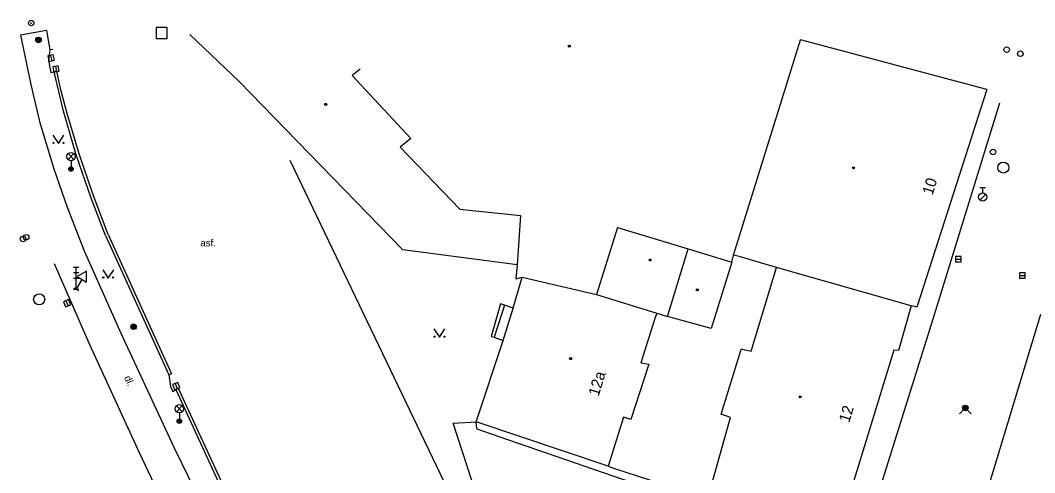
# Model space of a CAD drawing. Extents: x -598341 to -594502, y -1162301 to -1161406.
# Drawn here: x -597724.1 to -597632.3, y -1161447.8 to -1161406.9 of the extents above; entities that cross this region are included whole.
import ezdxf

# ---------------------------------------------------------------- set-up
doc = ezdxf.new("R2010")
doc.units = 0
for name, color, linetype in [('Vrstva 10', 7, 'Continuous'), ('Vrstva 11', 7, 'Continuous'), ('Vrstva 25', 7, 'Continuous'), ('Vrstva 26', 7, 'Continuous'), ('Vrstva 27', 7, 'Continuous'), ('Vrstva 28', 7, 'Continuous'), ('Vrstva 31', 7, 'Continuous'), ('Vrstva 33', 7, 'Continuous'), ('Vrstva 34', 7, 'Continuous'), ('Vrstva 36', 7, 'Continuous'), ('Vrstva 39', 7, 'Continuous'), ('Vrstva 40', 7, 'Continuous'), ('Vrstva 46', 7, 'Continuous'), ('Vrstva 5', 7, 'Continuous'), ('Vrstva 7', 7, 'Continuous')]:
    doc.layers.add(name, color=color, linetype=linetype)

msp = doc.modelspace()

# ---------------------------------------------------------------- linework, layer by layer
at = {"layer": 'Vrstva 10'}
for p, q in [((-597635.51, -1161414.4), (-597641.55, -1161433.95)), ((-597641.55, -1161433.95), (-597665.98, -1161512.17))]:
    msp.add_line(p, q, dxfattribs=at)
for points in [[(-597721.72, -1161407.83), (-597721.42, -1161409.57)], [(-597721.42, -1161409.57), (-597721.55, -1161410.54), (-597721.33, -1161411.63), (-597721.03, -1161411.55)], [(-597716.39, -1161426.38), (-597717.69, -1161422.99), (-597719.04, -1161419.07), (-597720.18, -1161415.11), (-597721.03, -1161411.55)], [(-597699.7, -1161419.56), (-597685.07, -1161450.16)], [(-597716.39, -1161426.38), (-597710.66, -1161438.99)], [(-597704.08, -1161465.47), (-597708.7, -1161455.79), (-597713.31, -1161446.04), (-597717.79, -1161436.33), (-597720.99, -1161428.95)], [(-597710.66, -1161438.99), (-597710.5, -1161440.03), (-597710.3, -1161440.48), (-597710.03, -1161440.32)], [(-597710.03, -1161440.32), (-597704.17, -1161453.05), (-597703.72, -1161454.73), (-597692.76, -1161476.87)]]:
    msp.add_lwpolyline(points, dxfattribs=at)
at = {"layer": 'Vrstva 11'}
for p, q in [((-597721.17, -1161409.54), (-597721.42, -1161409.57)), ((-597720.79, -1161411.5), (-597721.03, -1161411.55)), ((-597659.72, -1161428.8), (-597659.58, -1161428.16)), ((-597679.15, -1161429.04), (-597679.28, -1161430.29)), ((-597679.28, -1161430.29), (-597678.68, -1161430.13)), ((-597680.3, -1161432.69), (-597681.24, -1161435.57)), ((-597679.52, -1161432.94), (-597680.3, -1161432.69)), ((-597681.24, -1161435.57), (-597680.4, -1161435.88)), ((-597710.66, -1161438.99), (-597710.43, -1161438.89)), ((-597709.81, -1161440.19), (-597710.03, -1161440.32)), ((-597682.8, -1161443.87), (-597682.85, -1161443.23)), ((-597682.8, -1161443.87), (-597680.82, -1161444.57)), ((-597680.82, -1161444.57), (-597667.88, -1161449.04)), ((-597670.92, -1161447.25), (-597670.52, -1161447.4))]:
    msp.add_line(p, q, dxfattribs=at)
for points in [[(-597721.72, -1161407.83), (-597724.08, -1161408.25)], [(-597724.08, -1161408.25), (-597723.14, -1161412.69)], [(-597716.16, -1161426.29), (-597717.52, -1161422.7), (-597718.77, -1161418.99), (-597719.85, -1161415.32), (-597720.43, -1161413.19), (-597720.79, -1161411.5)], [(-597723.14, -1161412.69), (-597722.35, -1161416.05), (-597721.07, -1161420.34), (-597719.85, -1161423.8), (-597718.33, -1161427.77)], [(-597716.16, -1161426.29), (-597710.43, -1161438.89)], [(-597718.33, -1161427.77), (-597715, -1161435.22), (-597710.17, -1161445.59), (-597705.81, -1161454.55), (-597701.38, -1161464.17)], [(-597680.3, -1161432.69), (-597680.65, -1161432.57), (-597681.51, -1161435.52), (-597681.24, -1161435.57)], [(-597709.81, -1161440.19), (-597703.91, -1161452.98), (-597703.44, -1161454.64), (-597692.55, -1161476.76)], [(-597670.52, -1161447.4), (-597665.97, -1161448.88)]]:
    msp.add_lwpolyline(points, dxfattribs=at)
at = {"layer": 'Vrstva 25'}
for centre, radius in [((-597723.11, -1161407.14), 0.25), ((-597723.11, -1161407.14), 0.0303), ((-597722.45, -1161408.67), 0.25), ((-597722.45, -1161408.67), 0.2), ((-597722.45, -1161408.67), 0.15), ((-597722.45, -1161408.67), 0.1), ((-597722.45, -1161408.67), 0.05), ((-597713.85, -1161434.63), 0.25), ((-597713.85, -1161434.63), 0.2), ((-597713.85, -1161434.63), 0.15), ((-597713.85, -1161434.63), 0.1), ((-597713.85, -1161434.63), 0.05)]:
    msp.add_circle(centre, radius, dxfattribs=at)
at = {"layer": 'Vrstva 26'}
msp.add_lwpolyline([(-597711.82, -1161408.55), (-597710.82, -1161408.55), (-597710.82, -1161407.55), (-597711.82, -1161407.55)], close=True, dxfattribs=at)
at = {"layer": 'Vrstva 27'}
for p, q in [((-597721.363, -1161410.066), (-597721.256, -1161410.554)), ((-597720.923, -1161411.056), (-597720.816, -1161411.544)), ((-597639.49, -1161428.51), (-597638.99, -1161428.51)), ((-597633.69, -1161429.99), (-597633.19, -1161429.99)), ((-597719.971, -1161432.281), (-597719.769, -1161432.738)), ((-597710.085, -1161439.779), (-597709.895, -1161440.241))]:
    msp.add_line(p, q, dxfattribs=at)
for points in [[(-597721.607, -1161410.119), (-597721.501, -1161410.607), (-597721.012, -1161410.501), (-597721.118, -1161410.013)], [(-597721.167, -1161411.109), (-597721.061, -1161411.597), (-597720.572, -1161411.491), (-597720.678, -1161411.003)], [(-597639.49, -1161428.76), (-597638.99, -1161428.76), (-597638.99, -1161428.26), (-597639.49, -1161428.26)], [(-597633.69, -1161430.24), (-597633.19, -1161430.24), (-597633.19, -1161429.74), (-597633.69, -1161429.74)], [(-597720.2, -1161432.382), (-597719.997, -1161432.84), (-597719.54, -1161432.637), (-597719.743, -1161432.18)], [(-597710.316, -1161439.874), (-597710.126, -1161440.336), (-597709.664, -1161440.146), (-597709.854, -1161439.684)]]:
    msp.add_lwpolyline(points, close=True, dxfattribs=at)
for centre in [(-597635.16, -1161420.22), (-597722.39, -1161432.15)]:
    msp.add_circle(centre, 0.5, dxfattribs=at)
at = {"layer": 'Vrstva 28'}
for p, q in [((-597637.288, -1161423.162), (-597636.758, -1161422.632)), ((-597637.28, -1161422.015), (-597636.78, -1161422.015)), ((-597637.03, -1161422.515), (-597637.03, -1161422.015))]:
    msp.add_line(p, q, dxfattribs=at)
for centre, radius in [((-597634.86, -1161409.55), 0.25), ((-597633.62, -1161409.92), 0.25), ((-597636.09, -1161418.81), 0.25), ((-597637.03, -1161422.89), 0.375), ((-597723.57, -1161426.53), 0.25), ((-597723.85, -1161426.68), 0.25)]:
    msp.add_circle(centre, radius, dxfattribs=at)
at = {"layer": 'Vrstva 31'}
msp.add_lwpolyline([(-597639.14, -1161442.51), (-597638.61, -1161441.98), (-597638.08, -1161442.51)], dxfattribs=at)
for radius in [0.25, 0.18, 0.11]:
    msp.add_circle((-597638.61, -1161441.98), radius, dxfattribs=at)
at = {"layer": 'Vrstva 33'}
for p, q in [((-597719.775, -1161419.49), (-597719.245, -1161418.96)), ((-597719.775, -1161418.96), (-597719.245, -1161419.49)), ((-597719.51, -1161419.6), (-597719.51, -1161420.35)), ((-597719.29, -1161429.23), (-597718.79, -1161429.23)), ((-597719.29, -1161429.73), (-597718.79, -1161429.73)), ((-597719.04, -1161431.23), (-597719.04, -1161429.23)), ((-597719.29, -1161430.23), (-597718.79, -1161430.23)), ((-597719.29, -1161431.23), (-597718.79, -1161431.23)), ((-597709.975, -1161442.32), (-597709.445, -1161441.79)), ((-597709.975, -1161441.79), (-597709.445, -1161442.32)), ((-597709.71, -1161442.43), (-597709.71, -1161443.18))]:
    msp.add_line(p, q, dxfattribs=at)
for centre, radius in [((-597719.51, -1161419.225), 0.375), ((-597719.51, -1161420.35), 0.2), ((-597719.51, -1161420.35), 0.145), ((-597719.51, -1161420.35), 0.0876), ((-597709.71, -1161442.055), 0.375), ((-597709.71, -1161443.18), 0.2), ((-597709.71, -1161443.18), 0.145), ((-597709.71, -1161443.18), 0.0876)]:
    msp.add_circle(centre, radius, dxfattribs=at)
at = {"layer": 'Vrstva 34'}
for p, q in [((-597718.531, -1161430.348), (-597719.04, -1161431.23)), ((-597719.257, -1161431.105), (-597718.823, -1161431.355))]:
    msp.add_line(p, q, dxfattribs=at)
msp.add_lwpolyline([(-597718.964, -1161430.098), (-597718.098, -1161430.598), (-597718.098, -1161429.598)], close=True, dxfattribs=at)
at = {"layer": 'Vrstva 36'}
for points in [[(-597721.15, -1161417.29), (-597720.65, -1161418.04), (-597720.15, -1161417.29)], [(-597716.64, -1161429.47), (-597716.14, -1161430.22), (-597715.64, -1161429.47)], [(-597686.68, -1161434.83), (-597686.18, -1161435.58), (-597685.68, -1161434.83)]]:
    msp.add_lwpolyline(points, dxfattribs=at)
for centre in [(-597721.1, -1161417.99), (-597720.2, -1161417.99), (-597716.59, -1161430.17), (-597715.691, -1161430.17), (-597686.63, -1161435.53), (-597685.731, -1161435.53)]:
    msp.add_circle(centre, 0.05, dxfattribs=at)
at = {"layer": 'Vrstva 39'}
for centre, radius in [((-597674.43, -1161409.23), 0.09), ((-597674.43, -1161409.23), 0.0398), ((-597696.47, -1161414.5), 0.09), ((-597696.47, -1161414.5), 0.0398), ((-597648.71, -1161420.24), 0.09), ((-597648.71, -1161420.24), 0.0398), ((-597667.11, -1161428.59), 0.09), ((-597667.11, -1161428.59), 0.0398), ((-597662.85, -1161431.3), 0.09), ((-597662.85, -1161431.3), 0.0398), ((-597674.31, -1161437.52), 0.09), ((-597674.31, -1161437.52), 0.0398), ((-597653.54, -1161440.98), 0.09), ((-597653.54, -1161440.98), 0.0398)]:
    msp.add_circle(centre, radius, dxfattribs=at)
at = {"layer": 'Vrstva 5'}
for p, q in [((-597704.31, -1161412.44), (-597708.77, -1161408.18)), ((-597659.58, -1161428.16), (-597653.52, -1161408.65)), ((-597636.67, -1161413.16), (-597653.52, -1161408.65)), ((-597693.34, -1161411.33), (-597694.09, -1161411.89)), ((-597689.48, -1161427.68), (-597704.31, -1161412.44)), ((-597694.09, -1161411.89), (-597688.76, -1161417.6)), ((-597636.67, -1161413.16), (-597642.99, -1161432.86)), ((-597688.76, -1161417.6), (-597689.73, -1161418.38)), ((-597689.73, -1161418.38), (-597684.32, -1161423.98)), ((-597684.32, -1161423.98), (-597678.86, -1161424.57)), ((-597678.86, -1161424.57), (-597679.15, -1161429.04)), ((-597670.06, -1161425.64), (-597671.98, -1161431.71)), ((-597670.06, -1161425.64), (-597663.68, -1161427.59)), ((-597679.15, -1161429.04), (-597689.48, -1161427.68)), ((-597665.54, -1161433.69), (-597663.68, -1161427.59)), ((-597663.68, -1161427.59), (-597659.72, -1161428.8)), ((-597659.06, -1161428.26), (-597659.58, -1161428.16)), ((-597659.72, -1161428.8), (-597661.6, -1161434.79)), ((-597655.7, -1161429.26), (-597659.06, -1161428.26)), ((-597657.99, -1161436.85), (-597655.7, -1161429.26)), ((-597643.5, -1161432.75), (-597655.7, -1161429.26)), ((-597679.52, -1161432.94), (-597678.68, -1161430.13)), ((-597678.68, -1161430.13), (-597671.98, -1161431.71)), ((-597671.98, -1161431.71), (-597666.51, -1161433.4)), ((-597643.5, -1161432.75), (-597644.65, -1161436.79)), ((-597642.99, -1161432.86), (-597643.5, -1161432.75)), ((-597680.4, -1161435.88), (-597679.52, -1161432.94)), ((-597666.51, -1161433.4), (-597666.7, -1161433.88)), ((-597666.51, -1161433.4), (-597665.54, -1161433.69)), ((-597661.6, -1161434.79), (-597665.54, -1161433.69)), ((-597640.61, -1161462.69), (-597631.78, -1161433.48)), ((-597666.7, -1161433.88), (-597667.97, -1161437.9)), ((-597682.85, -1161443.23), (-597680.4, -1161435.88)), ((-597660.7, -1161442.53), (-597658.9, -1161436.77)), ((-597658.9, -1161436.77), (-597658.85, -1161436.62)), ((-597658.85, -1161436.62), (-597657.99, -1161436.85)), ((-597645.07, -1161436.76), (-597649.22, -1161450.27)), ((-597644.65, -1161436.79), (-597645.07, -1161436.76)), ((-597667.24, -1161438.03), (-597668.87, -1161443.02)), ((-597667.97, -1161437.9), (-597667.24, -1161438.03)), ((-597669.53, -1161442.83), (-597670.92, -1161447.25)), ((-597668.87, -1161443.02), (-597669.53, -1161442.83)), ((-597661.92, -1161450.2), (-597659.84, -1161442.84)), ((-597659.84, -1161442.84), (-597660.7, -1161442.53)), ((-597670.92, -1161447.25), (-597682.85, -1161443.23))]:
    msp.add_line(p, q, dxfattribs=at)
at = {"layer": 'Vrstva 7'}
for p, q in [((-597684.93, -1161443.36), (-597682.85, -1161443.23)), ((-597682.5, -1161450.79), (-597684.93, -1161443.36))]:
    msp.add_line(p, q, dxfattribs=at)

# ---------------------------------------------------------------- texts
at = {"layer": 'Vrstva 40'}
msp.add_text('asf.', height=0.65, dxfattribs=at).set_placement((-597707.81, -1161427.36))
msp.add_text('dl.', height=0.65, rotation=294.53497, dxfattribs=at).set_placement((-597714.72, -1161439.23))
at = {"layer": 'Vrstva 46'}
for s, rotation, p in [('10', 72.76, (-597641.57, -1161422.77)), ('12a', 72.95, (-597671.78, -1161440.98)), ('12', 72.95, (-597649.11, -1161443.37))]:
    msp.add_text(s, height=1, rotation=rotation, dxfattribs=at).set_placement(p)

doc.saveas('drawing.dxf')
